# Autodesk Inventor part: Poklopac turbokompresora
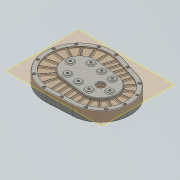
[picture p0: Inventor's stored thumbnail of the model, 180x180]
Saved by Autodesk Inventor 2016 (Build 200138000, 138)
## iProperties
Created: 2015-08
Part Number: Poklopac turbokompresora
Material: Generic
Document SubType Name: Modeling
Designer: stank
Density: 1 g/cm^3
Appearance: Default
Mass: 768.243 g
Surface Area: 1861.56 cm^2
Volume: 768.243 cm^3
Author: stank
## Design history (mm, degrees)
workplane "Work Plane3"
sketch "Sketch3"
  geometry: L1 (31.845, -105.063)-(-49.103, -109.733); L2 (26.085, -5.229)-(-52.114, 11.649); L3 (26.085, -5.229)-(-55.727, 5.076); L4 (30.981, -90.088)-(-49.967, -94.758); L5 (-25.39, 100.364)-(51.872, 75.766); L6 (56.422, 90.059)-(-20.839, 114.657); C1 r 9 at (26.085, -5.229) reference; C2 r 4.5 at (43.468, -93.366) reference; C3 r 4.5 at (-58.597, -126.199) reference; C4 r 4.5 at (-148.255, -75.856) reference; C5 r 4.5 at (-134.233, 101.873) reference; C6 r 4.5 at (-46.759, 125.523) reference; C7 r 4.5 at (25.538, 82.325) reference; A1 r 100 centre (26.085, -5.229) between (31.845, -105.063) and (56.422, 90.059); A2 r 115 centre (-55.727, 5.076) between (-20.839, 114.657) and (-49.103, -109.733); A3 r 85 centre (26.085, -5.229) between (30.981, -90.088) and (51.872, 75.766); A4 r 100 centre (-55.727, 5.076) between (-25.39, 100.364) and (-49.967, -94.758); 1 further point
  constraints: 12 end point, 8 point on circle, 6 tangent, 4 centre point, 2 parallel, 2 other
  dimensions: "d7" = 115 radius of A2; "d8" = 100 radius of A1; "d18" = 5 deg angle of L2 L3; "d26" = 15 distance between parallel lines of L1 L4; "d148" = 15 radial gap between concentric circles of A1 A3
extrude "Extrusion1" new body sketch "Sketch3" distance "d13" = 25; taper "d14" = 0 deg
sketch "Sketch7"
  geometry: L1 (56.422, 90.059)-(-20.839, 114.657) reference; L2 (-49.103, -109.733)-(31.845, -105.063) reference; C1 r 4 at (-41.402, 31.566) reference; C2 r 4 at (-38.197, -5.064) reference; C3 r 4 at (-13.762, -8.715) reference; C4 r 4 at (-4.556, 20.483) reference; C5 r 4 at (22.599, 34.619) reference; C6 r 4 at (51.797, 25.413) reference; C7 r 4 at (65.933, -1.742) reference; C8 r 4 at (56.727, -30.94) reference; C9 r 4 at (31.273, -44.891) reference; C10 r 4 at (0.374, -35.87) reference; A1 r 115 centre (-55.727, 5.076) between (-20.839, 114.657) and (-49.103, -109.733) reference; A2 r 100 centre (26.085, -5.229) between (31.845, -105.063) and (56.422, 90.059) reference; 1 further point
extrude "Extrusion3" join sketch "Sketch7" distance "d42" = 10; taper "d43" = 0 deg
sketch "Sketch8"
  geometry: L1 (30.981, -90.088)-(-49.967, -94.758) reference; L2 (-25.39, 100.364)-(51.872, 75.766) reference; C1 r 4 at (65.933, -1.742) reference; C2 r 4 at (56.727, -30.94) reference; C3 r 4 at (31.273, -44.891) reference; C4 r 4 at (0.374, -35.87) reference; C5 r 4 at (-13.762, -8.715) reference; C6 r 4 at (-38.197, -5.064) reference; C7 r 4 at (-4.556, 20.483) reference; C8 r 4 at (22.599, 34.619) reference; C9 r 4 at (51.797, 25.413) reference; C10 r 4 at (-41.402, 31.566) reference; C11 r 10 at (65.933, -1.742); C12 r 10 at (56.727, -30.94); C13 r 4 at (31.273, -44.891) reference; C14 r 10 at (31.273, -44.891); C15 r 10 at (0.374, -35.87); C16 r 4 at (-13.762, -8.715) reference; C17 r 10 at (-13.762, -8.715); C18 r 10 at (-38.197, -5.064); C19 r 10 at (-41.402, 31.566); C20 r 10 at (-4.556, 20.483); C21 r 4 at (22.599, 34.619) reference; C22 r 10 at (22.599, 34.619); C23 r 10 at (51.797, 25.413); A1 r 85 centre (26.085, -5.229) between (30.981, -90.088) and (51.872, 75.766) reference; A2 r 100 centre (-55.727, 5.076) between (-25.39, 100.364) and (-49.967, -94.758) reference; 1 further point
  constraints: 10 centre point, 10 coincident
  dimensions: "d44" = 20 diameter of C11; "d45" = 20 diameter of C12; "d46" = 20 diameter of C14; "d47" = 20 diameter of C15; "d48" = 20 diameter of C17; "d49" = 20 diameter of C20; "d50" = 20 diameter of C22; "d51" = 20 diameter of C23; "d52" = 20 diameter of C18; "d54" = 20 diameter of C19
extrude "Extrusion5" cut sketch "Sketch8" distance "d58" = 5; taper "d59" = 0 deg
sketch "Sketch10"
  geometry: C1 r 10 at (26.085, -5.229) reference; C2 r 11 at (26.085, -5.229); C3 r 16 at (26.085, -5.229); 1 further point
  constraints: 2 centre point, 2 coincident
  dimensions: "d60" = 1 radial gap between concentric circles of C1 C2; "d61" = 5 radial gap between concentric circles of C2 C3
extrude "Extrusion6" join sketch "Sketch10" distance "d62" = 3; taper "d63" = 0 deg
sketch "Sketch11"
  geometry: C1 r 11 at (0, 0) reference; 1 further point
extrude "Extrusion7" cut sketch "Sketch11" stored distance "d64" = 17; taper "d65" = 0 deg
chamfer "Chamfer3" distance "d71" = 2; stored, may be unused: second distance "d72" = 2, angle "d73" = 45 deg
workplane "Work Plane4"
sketch "Sketch12"
  geometry: L1 (26.085, -5.229)-(142.594, 145.734); L2 (26.085, -5.229)-(154.434, 22.85); L3 (26.085, -5.229)-(167.155, -24.202); L4 (26.085, -5.229)-(157.504, 77.979); L5 (101.371, 11.241)-(82.975, 7.217); L6 (89.461, -13.752)-(105.105, -15.856); L7 (75.965, 59.402)-(67.391, 48.291); L8 (92.041, 36.531)-(78.659, 28.059); L9 (-21.446, 112.751)-(55.816, 88.153) reference; L10 (31.73, -103.066)-(-49.218, -107.736) reference; L11 (-25.39, 100.364)-(51.872, 75.766) reference; L12 (30.981, -90.088)-(-49.967, -94.758) reference; L13 (-25.39, 100.364)-(51.872, 75.766) reference; L14 (-55.727, 5.076)-(-59.81, 104.993); L15 (-55.727, 5.076)-(-93.737, 97.571); L16 (-55.727, 5.076)-(-123.08, 78.992); L17 (-55.727, 5.076)-(-144.299, 51.499); L18 (-55.727, 5.076)-(-154.834, 18.406); L19 (-55.727, 5.076)-(-153.416, -16.295); L20 (-55.727, 5.076)-(26.085, -5.229); L21 (26.085, -5.229)-(51.872, 75.766); L22 (26.085, -5.229)-(51.872, 75.766); L23 (4.813, -2.549)-(31.782, 82.161); L24 (4.813, -2.549)-(8.443, -91.388); L25 (30.981, -90.088)-(-49.967, -94.758) reference; L26 (51.872, 75.766)-(-25.39, 100.364) reference; L27 (12.725, 88.229)-(-15.367, -0.007); L28 (-15.367, -0.007)-(-11.586, -92.543); L29 (-31.615, -93.699)-(-35.547, 2.534); L30 (-55.727, 5.076)-(-25.39, 100.364); L31 (-6.333, 94.296)-(-35.547, 2.534); L32 (49.768, 69.156)-(45.412, 55.475); L33 (49.768, 69.156)-(44.535, 52.72); L34 (29.678, 75.552)-(25.322, 61.871); L35 (9.933, 79.461)-(6.511, 68.711); L36 (-8.264, 88.229)-(-12.767, 74.086); L37 (-28.182, 91.595)-(-33.756, 74.086); L38 (-59.441, 95.979)-(-58.836, 81.156); L39 (-90.32, 89.255)-(-83.292, 72.154); L40 (-119.318, 74.864)-(-107.974, 62.414); L41 (-121.726, 39.668)-(-133.857, 46.026); L42 (-122.61, 14.072)-(-138.942, 16.268); L43 (-117.386, -8.413)-(-135.718, -12.423); L44 (-52.925, -63.49)-(-52.216, -80.841); L45 (-32.666, -67.96)-(-32.069, -82.577); L46 (-12.596, -67.814)-(-11.825, -86.696); L47 (7.37, -65.125)-(8.077, -82.428); L48 (26.085, -5.229)-(101.371, -44.688); L49 (26.085, -5.229)-(83.335, -68.057); L50 (26.085, -5.229)-(58.394, -83.849); L51 (26.085, -5.229)-(29.556, -90.158); L52 (-55.727, 5.076)-(-140.216, -48.418); L53 (-55.727, 5.076)-(-116.824, -74.089); L54 (-55.727, 5.076)-(-86.064, -90.211); L55 (-55.727, 5.076)-(-51.644, -94.84); L56 (83.335, -35.235)-(95.897, -41.818); L57 (65.44, -48.418)-(77.011, -61.116); L58 (49.052, -61.116)-(54.383, -74.089); L59 (28.634, -67.603)-(29.2, -81.44); L60 (-78.06, -65.073)-(-82.518, -79.075); L61 (-97.971, -49.661)-(-106.812, -61.116); L62 (-110.873, -29.84)-(-129.792, -41.818); C1 r 11 at (26.085, -5.229); C2 r 11 at (26.085, -5.229) reference; A1 r 100 centre (26.085, -5.229) between (31.845, -105.063) and (56.422, 90.059) reference; A2 r 115 centre (-55.727, 5.076) between (-20.839, 114.657) and (-49.103, -109.733) reference; A3 r 98 centre (26.085, -5.229) between (31.73, -103.066) and (55.816, 88.153) reference; A4 r 113 centre (-55.727, 5.076) between (-21.446, 112.751) and (-49.218, -107.736) reference; A5 r 85 centre (26.085, -5.229) between (30.981, -90.088) and (51.872, 75.766) reference; A6 r 100 centre (-55.727, 5.076) between (-25.39, 100.364) and (-49.967, -94.758) reference; A7 r 85 centre (26.085, -5.229) between (30.981, -90.088) and (51.872, 75.766) reference; A8 r 85 centre (26.085, -5.229) between (30.981, -90.088) and (51.872, 75.766) reference; A9 r 100 centre (-55.727, 5.076) between (-25.39, 100.364) and (-49.967, -94.758) reference
  constraints: 110 end point, 60 point on line, 18 point on circle, 6 parallel, 1 centre point, 1 coincident, 1 collinear, 1 perpendicular, 11 other
  dimensions: "d81" = 20 deg angle of L1 L4; "d82" = 20 deg angle of L2 L4; "d83" = 20 deg angle of L2 L3; "d194" = 20 deg angle of L14 L30; "d195" = 20 deg angle of L15 L14; "d196" = 20 deg angle of L15 L16; "d199" = 20 deg angle of L18 L17; "d200" = 20 deg angle of L18 L19; "d206" = 20 deg angle of L21 L1; "d207" = 20 deg angle of L16 L17; "d208" = 20 deg angle of L48 L3; "d209" = 20 deg angle of L49 L48; "d211" = 20 deg angle of L50 L49; "d212" = 20 deg angle of L51 L50; "d213" = 20 deg angle of L52 L19; "d214" = 20 deg angle of L53 L52; "d215" = 20 deg angle of L54 L53; "d216" = 20 deg angle of L54 L55; "d217" = 20 distance between parallel lines of L30 L31; "d218" = 20 distance between parallel lines of L27 L31; "d219" = 20 distance between parallel lines of L27 L23
  node "Projected Loop13"
sketch "Sketch13"
  geometry: L1 (26.085, -5.229)-(-31.513, 2.026); L2 (26.085, -5.229)-(-174.711, 20.063) reference; L3 (-55.727, 5.076)-(26.085, -5.229); L4 (-62.6, -49.493)-(19.212, -59.798); L5 (32.959, 49.34)-(-48.853, 59.645); A1 r 100 centre (-55.727, 5.076) between (-25.39, 100.364) and (-49.967, -94.758) reference; A2 r 55 centre (-55.727, 5.076) between (-48.853, 59.645) and (-62.6, -49.493); A3 r 55 centre (26.085, -5.229) between (19.212, -59.798) and (32.959, 49.34); 3 further points
  constraints: 12 end point, 4 point on circle, 4 tangent, 2 centre point, 2 collinear, 2 midpoint, 1 parallel
  dimensions: "d220" = 55 radius of A3
extrude "Extrusion8" join sketch "Sketch13" distance "d87" = 10; taper "d88" = 0 deg
fillet "Fillet9" dims "d99" = 1
fillet "Fillet10" dims "d100" = 2
chamfer "Chamfer4" distance "d138" = 1; stored, may be unused: second distance "d139" = 2, angle "d140" = 45 deg
fillet "Fillet12" dims "d150" = 2
sketch "Sketch18"
  geometry: 15 further points
hole "Hole1" sketch "Sketch18" at (-118.356, -16.851), (-100.183, -61.429), (-62.156, -90.949), (-82.286, 68.869), (-15.668, 95.688), (39.493, 111.849), (92.134, 106.755), (137.089, 76.099), (161.785, 25.463), (156.986, -32.481), (121.86, -80.308), (66.478, -102.387)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 diameter "d155" = 8; stored, may be unused: countersink angle "d159" = 90 deg, drill point angle "d161" = 118 deg; dims "d156" = 6, "d157" = 4, "d158" = 2, "d160" = 8
chamfer "Chamfer6" distance "d162" = 1; stored, may be unused: second distance "d163" = 2, angle "d164" = 45 deg
sketch "Sketch19"
  geometry: C1 r 11 at (26.085, -5.229) reference; C2 r 12 at (26.085, -5.229); 1 further point
  constraints: 1 centre point, 1 coincident
  dimensions: "d166" = 1 radial gap between concentric circles of C2 C1
extrude "Extrusion11" cut sketch "Sketch19" stored distance "d167" = 10; taper "d168" = 0 deg
workplane "Work Plane7"
sketch "Sketch21"
  geometry: L1 (-60, -32.012)-(-60, 42.797) reference; L2 (-60, 13.886)-(-59, 13.886); L3 (-59, 13.886)-(-59, 14.886); L4 (-59, 14.886)-(-60, 14.886); L5 (-60, 14.886)-(-60, 13.886); L6 (-47, 23.386)-(-60, 23.386); L7 (-60, 23.386)-(-60, 27.386); L8 (-60, 27.386)-(-47, 27.386); L9 (-47, 27.386)-(-47, 23.386); L10 (-50.113, -0.114)-(-87.752, -0.114) reference; 1 further point
  constraints: 18 end point, 4 horizontal, 4 parallel, 2 perpendicular, 2 point on line
  dimensions: "d176" = 28 diameter of L2 L10; "d177" = 1 distance of L2.start L2.end; "d178" = 1 distance of L2.end L3.end; "d179" = 4 distance between parallel lines of L8 L6; "d180" = 47 diameter of L6 L10; "d181" = 13 distance of L6.start L6.end
revolve "Revolution1" sketch "Sketch21" stored, may be unused: angle "d182" = 90 deg
workplane "Work Plane8"
sketch "Sketch22"
  geometry: L1 (1, 15)-(0, 15); L2 (0, 15)-(0, 16); L3 (0, 16)-(1, 16); L4 (1, 16)-(1, 15); L5 (1, 23.5)-(-12, 23.5); L6 (-12, 23.5)-(-12, 26.5); L7 (-12, 26.5)-(1, 26.5); L8 (1, 26.5)-(1, 23.5); L9 (-0.6, 23.5)-(-11.4, 23.5) reference; L10 (0, 0)-(17.307, 0); 4 further points; 2 other entities
  constraints: 20 end point, 4 horizontal, 4 parallel, 2 perpendicular, 1 point on line, 5 other
  dimensions: "d183" = 1 distance of L3.end L1.start; "d184" = 1 distance of L1.start L1.end; "d185" = 30 diameter of L1 L10; "d186" = 47 diameter of L5 L10; "d187" = 13 distance between parallel lines of L8 L6; "d188" = 3 distance of L7.end L5.start
revolve "Revolution2" sketch "Sketch22" stored, may be unused: angle "d189" = 90 deg
fillet "Fillet14" dims "d190" = 2
chamfer "Chamfer7" distance "d191" = 2; stored, may be unused: second distance "d192" = 2, angle "d193" = 45 deg
feature "Rib7" dims "d227" = 5, "d228" = 1, "d229" = 0, "d230" = 0, "d231" = 1, "d232" = 1
feature "Rib8" dims "d233" = 5, "d234" = 1, "d235" = 0, "d236" = 0, "d237" = 1, "d238" = 1
feature "Rib9" dims "d239" = 5, "d240" = 1, "d241" = 0, "d242" = 0, "d243" = 1, "d244" = 1
feature "Rib10" dims "d245" = 5, "d246" = 1, "d247" = 0, "d248" = 0, "d249" = 1, "d250" = 1
fillet "Fillet15" dims "d251" = 2
fillet "Fillet16" dims "d252" = 0.5
sketch "Sketch23"
  geometry: L1 (19.462, -57.813)-(-62.35, -47.508) reference; L2 (-49.103, 57.661)-(32.709, 47.356) reference; L3 (26.085, -5.229)-(-55.727, 5.076); L4 (26.085, -5.229)-(-55.727, 5.076); L5 (30.459, 29.497)-(-51.353, 39.802); L6 (-60.101, -29.649)-(21.712, -39.954); C1 r 12 at (26.085, -5.229) reference; A1 r 53 centre (-55.727, 5.076) between (-49.103, 57.661) and (-62.35, -47.508) reference; A2 r 53 centre (26.085, -5.229) between (19.462, -57.813) and (32.709, 47.356) reference; A3 r 35 centre (26.085, -5.229) between (21.712, -39.954) and (30.459, 29.497); A4 r 35 centre (-55.727, 5.076) between (-51.353, 39.802) and (-60.101, -29.649); 10 further points
  constraints: 10 end point, 6 point on circle, 4 coincident, 4 tangent, 3 midpoint, 2 centre point, 2 equal length
  dimensions: "d253" = 35 radius of A3
hole "Hole3" sketch "Sketch23" at (60.811, -9.603), (-90.452, 9.45), (30.459, 29.497), (21.712, -39.954), (-60.101, -29.649), (-51.353, 39.802), (-10.447, 34.649), (-19.195, -34.802) diameter "d254" = 8; stored, may be unused: countersink angle "d258" = 90 deg, drill point angle "d260" = 118 deg; dims "d255" = 6, "d256" = 4, "d257" = 2, "d259" = 10
sketch "Sketch24"
  geometry: C1 r 4 at (-51.353, 39.802) reference; C2 r 4 at (-10.447, 34.649) reference; C3 r 4 at (30.459, 29.497) reference; C4 r 4 at (60.811, -9.603) reference; C5 r 4 at (21.712, -39.954) reference; C6 r 4 at (-19.195, -34.802) reference; C7 r 4 at (-60.101, -29.649) reference; C8 r 4 at (-90.452, 9.45) reference; C9 r 10 at (-51.353, 39.802); C10 r 10 at (-10.447, 34.649); C11 r 10 at (30.459, 29.497); C12 r 10 at (60.811, -9.603); C13 r 10 at (21.712, -39.954); C14 r 10 at (-19.195, -34.802); C15 r 10 at (-60.101, -29.649); C16 r 10 at (-90.452, 9.45); 1 further point
  constraints: 8 centre point, 8 coincident
  dimensions: "d261" = 20 diameter of C9; "d262" = 20 diameter of C10; "d263" = 20 diameter of C11; "d264" = 20 diameter of C12; "d265" = 20 diameter of C13; "d266" = 20 diameter of C14; "d267" = 20 diameter of C15; "d268" = 20 diameter of C16
extrude "Extrusion12" join sketch "Sketch24" distance "d269" = 3; taper "d270" = 0 deg
fillet "Fillet17" dims "d271" = 3
chamfer "Chamfer8" distance "d272" = 2; stored, may be unused: second distance "d273" = 2, angle "d274" = 45 deg
body "Solid1"
node "Reference1"
node "Reference2"
node "Reference12"
node "Reference13"
node "Reference14"
node "Reference15"
node "Reference16"
node "Reference17"
node "Reference25"
node "Reference26"
node "Reference27"
node "Reference28"
node "Reference29"
node "Reference30"
node "Reference31"
node "Reference32"
node "Reference33"
node "Reference34"
node "Reference35"
node "Reference41"
node "Reference42"
node "Reference43"
node "Reference44"
node "Reference46"
node "Reference48"
node "Reference49"
node "Reference50"
node "Reference51"
node "Reference52"
node "Reference53"
node "Reference54"
node "Reference55"
node "Reference56"
node "Reference57"
node "Projected Loop14"
other parameters: "d89" = 4
